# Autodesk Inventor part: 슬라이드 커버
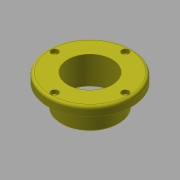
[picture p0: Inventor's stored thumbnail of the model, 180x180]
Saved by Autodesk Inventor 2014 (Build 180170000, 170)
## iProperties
Created: 2015-10
Part Number: 슬라이드 커버
Document SubType Name: Modeling
Designer: mdu
Density: 7.86 g/cm^3
Material: 강철, 연강
Mass: 633.012 g
Surface Area: 239.629 cm^2
Volume: 80.5358 cm^3
Appearance: 밝은 황색
Author: mdu
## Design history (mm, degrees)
sketch "스케치1"
  geometry: C1 r 47.5 at (0, 0); C2 r 32.5 at (0, 0); 1 further point
  constraints: 2 centre point, 2 coincident
  dimensions: "d33" = 95 diameter of C1; "d35" = 65 diameter of C2
extrude "돌출1" new body sketch "스케치1" distance "d0" = 10; taper "d1" = 0 deg
extrude "돌출2" join sketch "스케치1" distance "d2" = 25; taper "d3" = 0 deg
hole "구멍1" diameter "d6" = 50; stored, may be unused: countersink angle "d10" = 90 deg, drill point angle "d12" = 118 deg; dims "d4" = 10, "d5" = 10, "d7" = 6, "d8" = 4, "d9" = 2, "d11" = 8
sketch "스케치2" dims "d36" = 80
  geometry: 4 further points
  constraints: 2 coincident, 2 vertical alignment, 2 other
hole "구멍2" sketch "스케치2" at (0, 40) diameter "d13" = 4.5; stored, may be unused: countersink angle "d17" = 90 deg, drill point angle "d19" = 118 deg; dims "d14" = 6, "d15" = 8, "d16" = 4.4, "d18" = 8
fillet "모깎기1" dims "d23" = 3
chamfer "모따기1" distance "d24" = 1; stored, may be unused: second distance "d25" = 2, angle "d26" = 45 deg
sketch "스케치3"
  geometry: C1 r 25 at (0, 0); C2 r 30 at (0, 0); C3 r 26 at (0, 0) reference; 1 further point
  constraints: 2 centre point, 2 coincident
  dimensions: "d27" = 60 diameter of C2
extrude "돌출3" cut sketch "스케치3" distance "d28" = 3; taper "d29" = 0 deg
chamfer "모따기2" distance "d30" = 1; stored, may be unused: second distance "d31" = 2, angle "d32" = 45 deg
node "솔리드1"
pattern_circular "원형 패턴1" dims angle "d21" = 360 deg
